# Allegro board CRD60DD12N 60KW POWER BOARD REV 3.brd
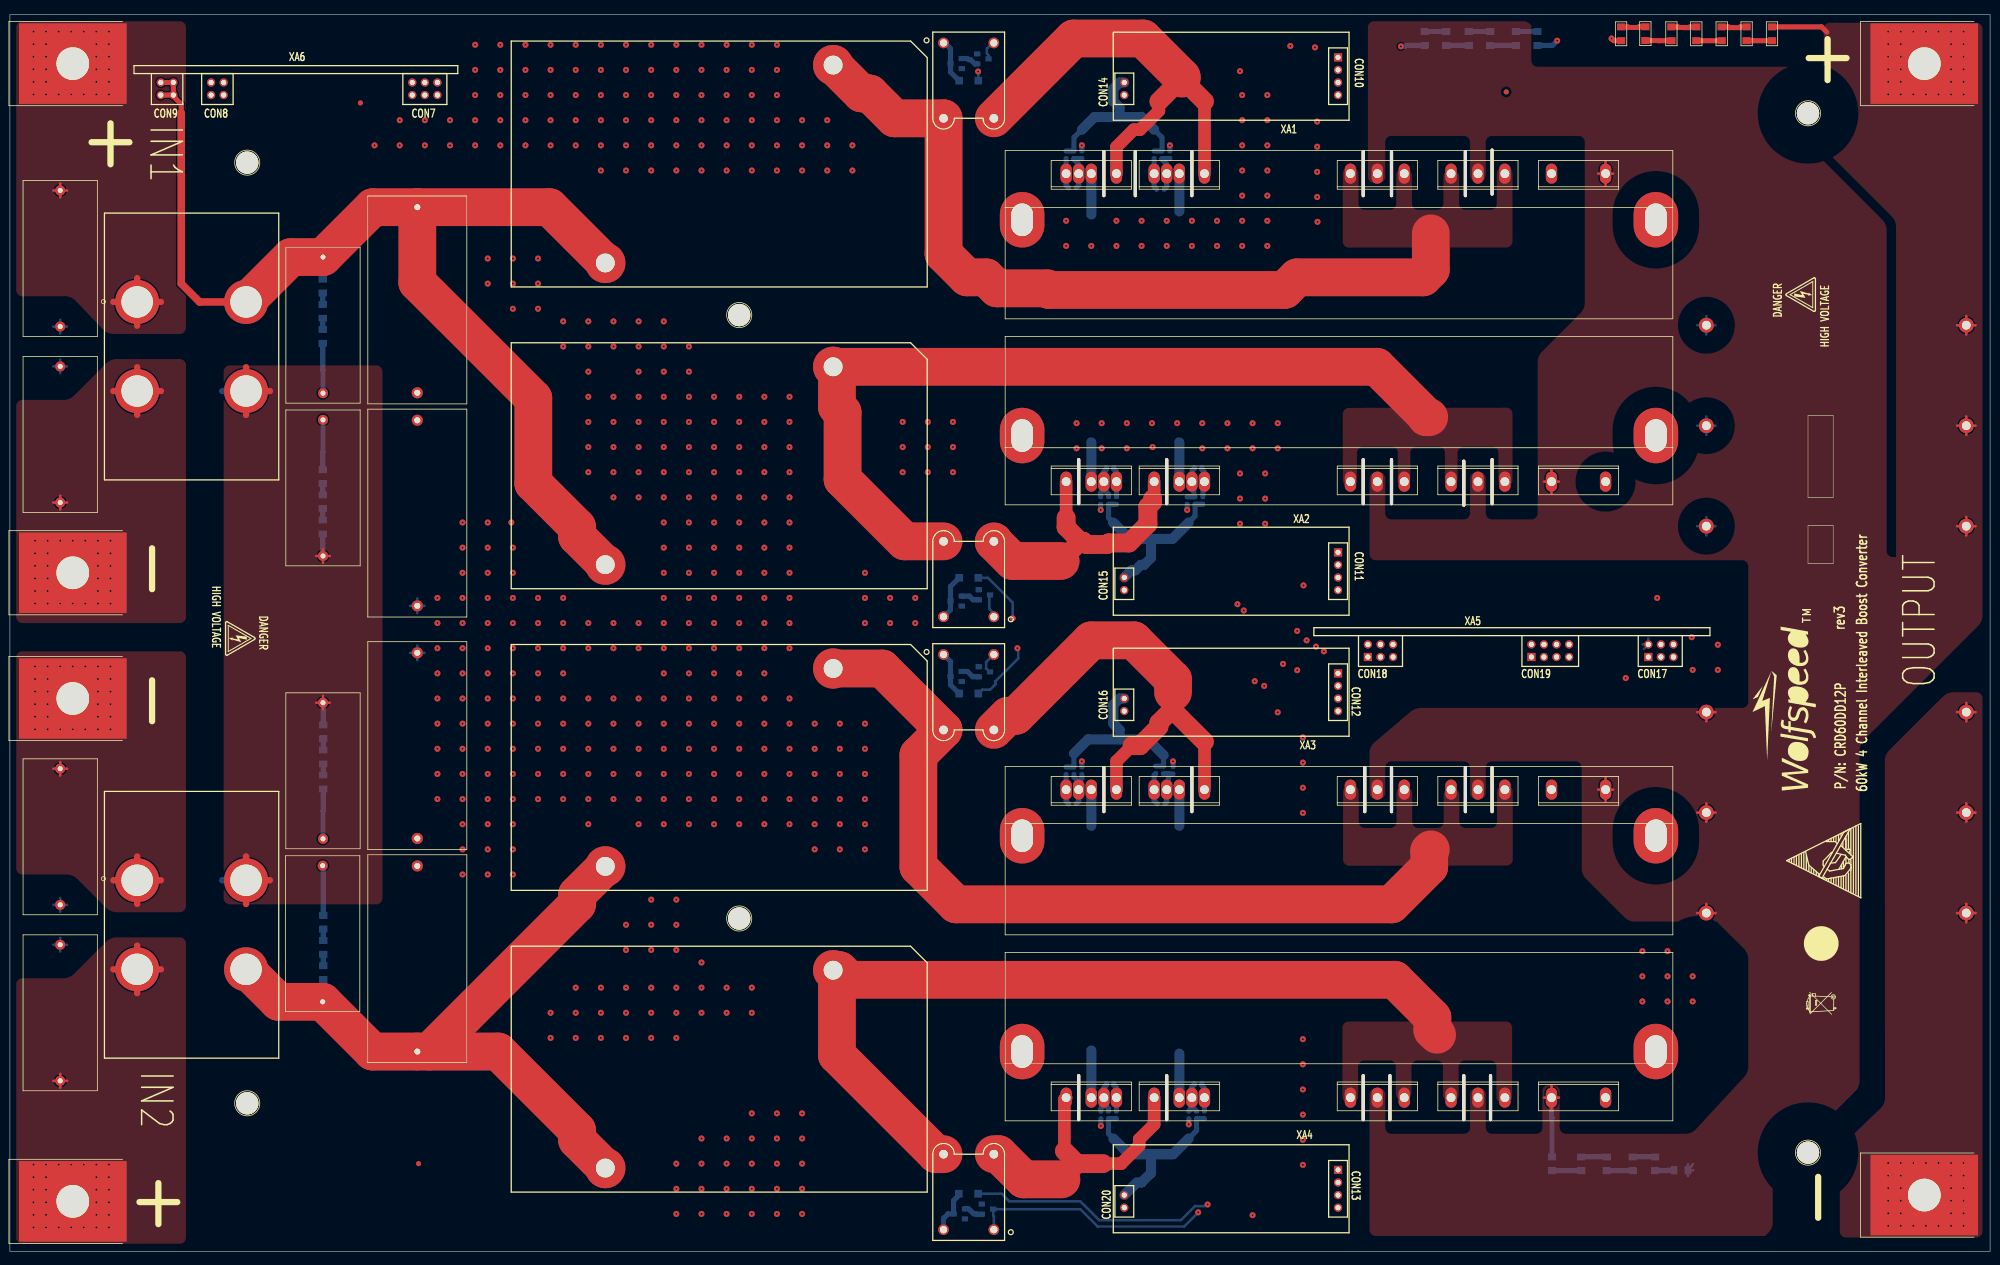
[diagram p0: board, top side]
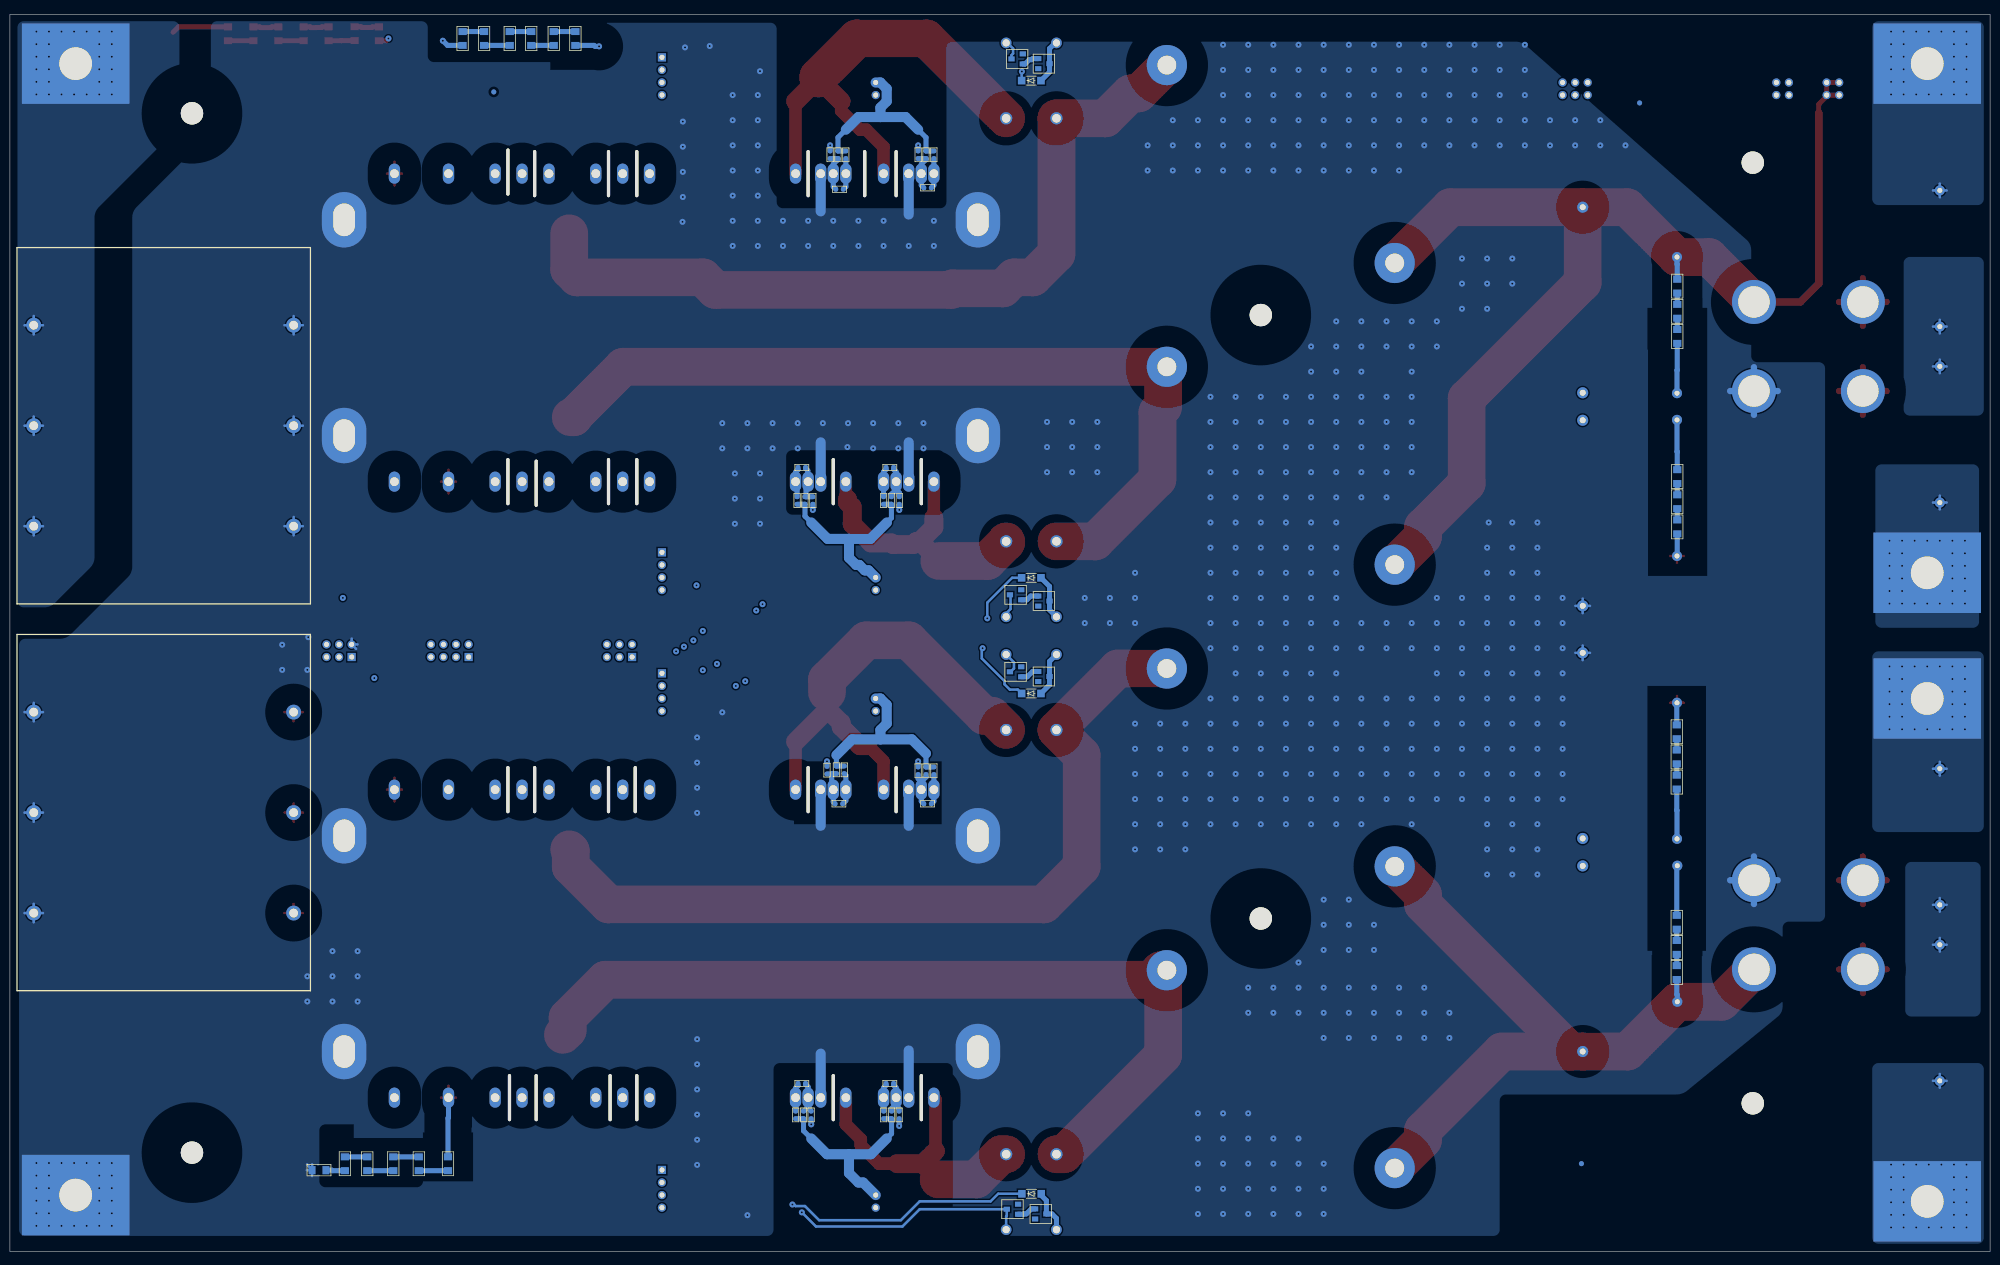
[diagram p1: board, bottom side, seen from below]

Outline 400 x 250 mm; copper layers: TOP, ART02, ART03, BOTTOM. Coordinates in mm from the lower left corner of the outline.
Outline path: rectangle 0,0 400,250

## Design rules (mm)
net group PH1H_SW: nets N02836 N03399
net group PH1L_SW: nets N08631 N08663
net group PH2H_SW: nets N12716 N12748
net group PH2L_SW: nets N13264 N13296
net group 1206_PAD: nets N05226 N09826 N10005 N10007 N12260 N12055866 N12061792 N12061794 N12062725 N12062727 N12099195 N12120580 N12122904 N12122941 N12122950 N12123059 N12123067
net group HVDC: nets HV_L1_IN HV_L3_IN N05349 N12168
net group LVDC: nets +12V_HV +12V_RTN N00267 V_IN_SENSE V_OUT_SENSE
net group PH1H_CTRL: nets G1H N01331 N01554 N02735 N03711 N03751 N12047025 PH1H_CS PH1H_CS_RTN PWM1H
net group PH1L_CTRL: nets G1L N08439 N08479 N08627 N08687 N08743 N12048829 PH1L_CS PH1L_CS_RTN PWM1L
net group PH2H_CTRL: nets G2H N12524 N12564 N12712 N12776 N12832 N12042408 PH2H_CS PH2H_CS_RTN PWM2H
net group PH2L_CTRL: nets G2L N13072 N13096 N13260 N13300 N13376 N12045153 PH2L_CS PH2L_CS_RTN PWM2L
nets with their own width: min track width 0.508; nets G1H_RTN G1L_RTN G2H_RTN G2L_RTN GND_SIGNAL N00134 N00143 N00161 N003141 N004301 N004861 N005141 N12176 N12212 N122921 N123081 N123401 N123561 PV_-VE

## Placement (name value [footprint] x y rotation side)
C1  22uF  [RAD_37MM5_L42_W20]  82.3 192.28 270 top
C2  22uF  [RAD_37MM5_L42_W20]  82.3 149.22 270 top
C3  22uF  [RAD_37MM5_L42_W20]  82.3 59.18 90 top
C4  22uF  [RAD_37MM5_L42_W20]  82.3 102.23 90 top
C5  100uF  [CAP_6L_52P5X20P3]  368.94 166.88 180 bottom
C6  100uF  [CAP_6L_52P5X20P3]  368.94 88.71 0 bottom
C9  1.5nF  [0603]  232.41 214.66 0 bottom
C10  1.5nF  [0603]  240.03 158.43 180 bottom
C19  1.5nF  [0603]  214.63 214.95 0 bottom
C20  1.5nF  [0603]  222.25 158.43 180 bottom
C21  1.5nF  [0603]  214.63 90.49 0 bottom
C22  1.5nF  [0603]  232.54 90.49 0 bottom
C23  1.5nF  [0603]  222.25 33.97 180 bottom
C24  1.5nF  [0603]  240.03 33.97 180 bottom
CON1  +PV_1  [PWR_CON_50A]  12.7 240.03 0 top
CON2  -PV_1  [PWR_CON_50A]  12.7 137.16 0 top
CON3  +PV_2  [PWR_CON_50A]  12.7 10.16 0 top
CON4  -PV_2  [PWR_CON_50A]  12.7 111.76 0 top
CON5  HVDC_OUT  [PWR_CON_50A]  386.71 240.03 0 top
CON6  PV_-VE  [PWR_CON_50A]  386.71 11.43 0 top
CT1  -  [CT_PE-67200NL]  193.68 236.6 90 top
CT2  -  [CT_PE-67200NL]  193.68 135.89 270 top
CT3  -  [CT_PE-67200NL]  193.68 113.03 90 top
CT4  -  [CT_PE-67200NL]  193.68 12.06 270 top
D1  C4D10120D  [TO-247-3L]  276.23 217.81 180 top
D2  C4D10120D  [TO-247-3L]  276.23 155.57 0 top
D3  C4D10120D  [TO-247-3L]  276.23 93.34 180 top
D4  C4D10120D  [TO-247-3L]  276.23 31.11 0 top
D11  BAS16  [SOT-23]  191.13 240.03 270 bottom
D12  BAV20W-7F  [SOD-123]  193.68 236.6 0 bottom
D15  BAS16  [SOT-23]  191.13 131.44 270 bottom
D16  BAV20W-7F  [SOD-123]  193.68 136.14 0 bottom
D19  BAS16  [SOT-23]  191.13 116.2 270 bottom
D20  BAV20W-7F  [SOD-123]  193.68 112.78 0 bottom
D23  BAS16  [SOT-23]  191.77 7.62 270 bottom
D24  BAV20W-7F  [SOD-123]  193.63 11.7 0 bottom
D25  C4D10120D  [TO-247-3L]  296.55 217.81 180 top
D26  C4D10120D  [TO-247-3L]  296.55 155.57 0 top
D27  C4D10120D  [TO-247-3L]  296.55 93.34 180 top
D28  C4D10120D  [TO-247-3L]  296.55 31.11 0 top
D29  DLA60I1200HA  [TO-247-2L]  316.87 217.81 180 top
D30  DLA60I1200HA  [TO-247-2L]  316.87 155.57 0 top
D31  DLA60I1200HA  [TO-247-2L]  316.87 93.34 180 top
D32  DLA60I1200HA  [TO-247-2L]  316.87 31.11 0 top
FB1  BEAD  [0603]  213.36 221.62 270 bottom
FB2  BEAD  [0603]  231.14 221.62 270 bottom
FB3  BEAD  [0603]  223.52 151.76 90 bottom
FB4  BEAD  [0603]  240.98 151.76 90 bottom
FB5  BEAD  [0603]  213.36 97.16 270 bottom
FB6  BEAD  [0603]  231.46 97.35 270 bottom
FB7  BEAD  [0603]  223.49 27.62 90 bottom
FB8  BEAD  [0603]  241.27 27.62 90 bottom
HS1  HEAT_SINK  [AAVID_78010_L135MM]  268.48 208.48 90 top
HS2  HEAT_SINK  [AAVID_78010_L135MM]  268.48 164.89 270 top
HS3  HEAT_SINK  [AAVID_78010_L135MM]  268.48 84.03 90 top
HS4  HEAT_SINK  [AAVID_78010_L135MM]  268.48 40.43 270 top
L1  INDUCTOR  [PWR_IND_T26586]  143.28 219.75 270 top
L2  INDUCTOR  [PWR_IND_T26586]  143.28 158.79 270 top
L3  INDUCTOR  [PWR_IND_T26586]  143.28 97.83 270 top
L4  INDUCTOR  [PWR_IND_T26586]  143.28 36.87 270 top
NOREF  -  []  82.55 17.78 0 top
NOREF#2  -  [unnamed#2]  233.68 155.57 90 top
NOREF#3  -  [unnamed#2]  273.37 31.11 90 top
NOREF#4  -  []  -155.26 -223.84 0 top
NOREF#5  -  [unnamed#2]  279.08 217.81 90 top
NOREF#6  -  [unnamed#2]  220.98 217.81 90 top
NOREF#7  -  []  365.66 62.76 90 top
NOREF#8  -  []  70.8 232.09 0 top
NOREF#9  -  [unnamed#2]  279.08 155.57 90 top
NOREF#10  -  [unnamed#2]  299.4 93.34 90 top
NOREF#11  -  [unnamed#2]  238.76 93.34 90 top
NOREF#12  -  []  369.43 79.51 90 top
NOREF#13  -  [unnamed#2]  233.68 31.11 90 top
NOREF#14  -  [unnamed#2]  220.98 93.34 90 top
NOREF#15  -  [unnamed#2]  279.08 93.34 90 top
NOREF#16  -  []  364.49 190.18 90 top
NOREF#17  -  []  365.77 52.72 90 top
NOREF#18  -  [unnamed#2]  273.37 217.81 90 top
NOREF#19  -  [unnamed#2]  47.94 220.03 0 top
NOREF#20  -  [unnamed#2]  299.4 218.12 90 top
NOREF#21  -  []  0 250 0 top
NOREF#22  -  [unnamed#2]  227.33 217.81 90 top
NOREF#23  -  []  302.26 234.31 0 top
NOREF#24  -  [unnamed#2]  299.08 31.11 90 top
NOREF#25  -  [unnamed#2]  294 217.81 90 top
NOREF#26  -  []  43.8 127.06 270 top
NOREF#27  -  [unnamed#2]  363.22 230 0 top
NOREF#28  -  [unnamed#2]  363.22 20 0 top
NOREF#29  -  []  0 0 90 top
NOREF#30  -  [unnamed#2]  294 93.34 90 top
NOREF#31  -  [unnamed#2]  215.9 155.57 90 top
NOREF#32  -  []  366.08 91.44 90 top
NOREF#33  -  [unnamed#2]  273.69 93.34 90 top
NOREF#34  -  [unnamed#2]  47.94 29.97 0 top
NOREF#35  -  [unnamed#2]  293.69 155.26 90 top
NOREF#36  -  [unnamed#2]  215.9 31.11 90 top
NOREF#37  -  [unnamed#2]  147.32 189.23 0 top
NOREF#38  -  [unnamed#2]  293.69 31.11 90 top
NOREF#39  -  [unnamed#2]  299.4 155.57 90 top
NOREF#40  -  [unnamed#2]  278.76 31.11 90 top
NOREF#41  -  [unnamed#2]  147.32 67.31 0 top
NOREF#42  -  []  -5.08 -44.45 0 top
NOREF#43  -  [unnamed#2]  238.76 217.81 90 top
NOREF#44  -  [unnamed#2]  273.37 155.57 90 top
Q1  NMOS 4-lead  [TO-247-4L]  218.44 217.81 180 top
Q2  NMOS 4-lead  [TO-247-4L]  236.22 217.81 180 top
Q3  NMOS 4-lead  [TO-247-4L]  218.44 155.57 0 top
Q4  NMOS 4-lead  [TO-247-4L]  236.22 155.57 0 top
Q5  NMOS 4-lead  [TO-247-4L]  218.44 93.34 180 top
Q6  NMOS 4-lead  [TO-247-4L]  236.22 93.34 180 top
Q7  NMOS 4-lead  [TO-247-4L]  218.44 31.11 0 top
Q8  NMOS 4-lead  [TO-247-4L]  236.22 31.11 0 top
R1  1R  [0603]  216.53 221.62 90 bottom
R2  1R  [0603]  234.31 221.62 90 bottom
R3  1R  [0603]  220.34 151.76 270 bottom
R4  1R  [0603]  237.81 151.76 270 bottom
R5  1R  [0603]  216.53 97.16 90 bottom
R6  1R  [0603]  234.95 97.28 90 bottom
R7  10K  [0603]  214.95 221.62 270 bottom
R8  1R  [0603]  220.37 27.62 270 bottom
R9  1R  [0603]  238.15 27.62 270 bottom
R10  10K  [0603]  232.73 221.62 270 bottom
R11  200K  [1206]  325.46 246.06 270 top
R12  1.07M  [1206]  340.65 246.06 90 top
R13  10K  [0603]  221.93 151.76 90 bottom
R14  1.07M  [1206]  285.78 245.11 90 bottom
R15  1.07M  [1206]  290.14 245.11 270 bottom
R16  10K  [0603]  239.4 151.76 90 bottom
R17  1.07M  [1206]  294.69 245.11 90 bottom
R18  1.07M  [1206]  299.03 245.11 270 bottom
R19  10K  [0603]  214.95 97.16 270 bottom
R20  1.07M  [1206]  304.22 245.11 90 bottom
R21  1.07M  [1206]  308.56 245.11 270 bottom
R22  10K  [0603]  233.04 97.35 270 bottom
R25  10K  [0603]  221.91 27.62 90 bottom
R28  10K  [0603]  239.69 27.62 90 bottom
R29  1.07M  [1206]  63.2 195.07 270 bottom
R30  1.07M  [1206]  63.2 189.99 270 bottom
R31  1.07M  [1206]  63.2 184.91 270 bottom
R32  1.07M  [1206]  63.2 156.59 270 bottom
R33  1.07M  [1206]  63.2 151.51 270 bottom
R34  1.07M  [1206]  63.2 146.43 270 bottom
R35  1.07M  [1206]  63.3 56.39 90 bottom
R36  1.07M  [1206]  63.3 61.47 90 bottom
R37  1.07M  [1206]  63.3 66.55 90 bottom
R38  1.07M  [1206]  63.3 94.87 90 bottom
R39  1.07M  [1206]  63.3 99.95 90 bottom
R40  1.07M  [1206]  63.3 105.03 90 bottom
R41  1.07M  [1206]  311.51 17.75 270 bottom
R42  1.07M  [1206]  317.4 17.75 90 bottom
R43  1.07M  [1206]  322.55 17.75 270 bottom
R44  1.07M  [1206]  327.81 17.75 90 bottom
R45  1.07M  [1206]  332.33 17.75 270 bottom
R46  1.07M  [1206]  337.57 16.46 0 bottom
R59  1.07M  [1206]  355.94 246.06 270 top
R60  1.07M  [1206]  350.81 246.06 90 top
R61  1.07M  [1206]  345.78 246.06 270 top
R63  1.07M  [1206]  335.62 246.06 270 top
R64  1.07M  [1206]  330.37 246.09 90 top
XA1  CGD15SG00D2_Gate Driver  [CGD15SG00D2_GATE_DRIVER]  268.29 241.3 180 top
XA2  CGD15SG00D2_Gate Driver  [CGD15SG00D2_GATE_DRIVER]  268.29 141.29 180 top
XA3  CGD15SG00D2_Gate Driver  [CGD15SG00D2_GATE_DRIVER]  268.29 116.84 180 top
XA4  CGD15SG00D2_Gate Driver  [CGD15SG00D2_GATE_DRIVER]  268.29 16.51 180 top
XA5  -  [CRD50DD12N_CTRL]  274.32 120.14 0 top
XA6  FLYBACK_PS  [FLYBACK_DAUGHTER_BRD]  30.48 233.68 0 top
XC1  2.2uF  [RAD_27MM5_L31_5_W15]  10.16 200.66 270 top
XC2  2.2uF  [RAD_27MM5_L31_5_W15]  10.16 165.1 270 top
XC3  2.2uF  [RAD_27MM5_L31_5_W15]  63.25 187.2 270 top
XC4  2.2uF  [RAD_27MM5_L31_5_W15]  63.25 154.31 270 top
XC5  2.2uF  [RAD_27MM5_L31_5_W15]  10.16 48.26 90 top
XC6  2.2uF  [RAD_27MM5_L31_5_W15]  10.16 83.82 90 top
XC7  2.2uF  [RAD_27MM5_L31_5_W15]  63.18 64.23 90 top
XC8  2.2uF  [RAD_27MM5_L31_5_W15]  63.25 97.16 90 top
XL1  CHOKE CM  [CM_CHOKE_T46592]  36.7 182.88 270 top
XL2  CHOKE CM  [CM_CHOKE_T46592]  36.7 66.04 270 top
ZD5  33V  [SOT-23]  196.53 240.98 90 bottom
ZD6  33V  [SOT-23]  196.85 132.72 90 bottom
ZD7  33V  [SOT-23]  196.85 117.16 90 bottom
ZD8  33V  [SOT-23]  197.49 8.57 90 bottom

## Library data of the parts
C1-C4 C9 C10 C19-C24 XC1-XC8 = CAPACITOR NON-POL
C5 C6 = CAP NP 6L
CON1-CON6 = T POINT S_0
CT1-CT4 = CT_PE-67200NL
D1-D4 D25-D28 = C4D10120D
D11 D15 D19 D23 = DIODE_SO-23
D12 D16 D20 D24 = DIODE SCHOTTKY
D29-D32 = DIODE_2
FB1-FB8 = BEAD
HS1-HS4 = HEAT_SINK_2
L1-L4 = INDUCTOR FERRITE_0
Q1-Q8 = NMOS 4-lead
R1-R22 R25 R28-R46 R59-R61 R63 R64 = RESISTOR
XA1-XA4 = CGD15SG00D2_Gate Driver_0
XA5 = CRD50DD12N_CTRL
XA6 = FLYBACK_PS
XL1 XL2 = CHOKE CM
ZD5-ZD8 = DIODE ZENER SO-23

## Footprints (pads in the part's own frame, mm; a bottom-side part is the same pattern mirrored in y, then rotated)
0603
  rect 0.762x0.813 smd: 1(-0.762,0) 2(0.762,0)
1206
  rect 1.397x1.651 smd: 1(-1.397,0) 2(1.397,0)
AAVID_78010_L135MM
  oval 11.201x8.992 hole 6.604x4.394: 1(0,-64.008) 2(0,64.008)
CAP_6L_52P5X20P3
  round 2.997 hole 1.778: 1(-26.251,20.3) 2(26.251,20.3) 3(-26.251,0) 4(26.251,0) 5(-26.251,-20.3) 6(26.251,-20.3)
CGD15SG00D2_GATE_DRIVER
  rect 1.651x1.651 hole 1.041: 1(0,0)
  round 1.651 hole 1.041: 2(0,2.54) 3(0,5.08) 4(0,7.62) 5(43.18,5.08) 6(43.18,7.62)
CM_CHOKE_T46592
  round 8.89 hole 6.35: 1(-9,-11) 2(9,-11) 3(9,11) 4(-9,11)
CRD50DD12N_CTRL
  rect 1.651x1.651 hole 1.041: 1(0,0) 7(33.02,0) 15(56.642,0)
  round 1.651 hole 1.041: 2(0,2.54) 3(2.54,0) 4(2.54,2.54) 5(5.08,0) 6(5.08,2.54) 8(33.02,2.54) 9(35.56,0) 10(35.56,2.54) 11(38.1,0) 12(38.1,2.54) 13(40.64,0) 14(40.64,2.54) 16(56.642,2.54) 17(59.182,0) 18(59.182,2.54) 19(61.722,0) 20(61.722,2.54)
CT_PE-67200NL
  round 2.464 hole 1.753: 1(-7.62,5.08) 2(-7.62,-5.08)
  round 2.159 hole 1.473: 3(7.62,5.08) 4(7.62,-5.08)
FLYBACK_DAUGHTER_BRD
  round 1.651 hole 1.041: 1(0,0) 2(0,2.54) 3(2.54,0) 4(2.54,2.54) 5(10.16,0) 6(10.16,2.54) 7(12.7,0) 8(12.7,2.54) 9(50.8,0) 10(50.8,2.54) 11(53.34,0) 12(53.34,2.54) 13(55.88,0) 14(55.88,2.54)
PWR_CON_50A
  rect 21.717x16.256 hole 6.604: 1(0,0)
PWR_IND_T26586
  round 8.128 hole 3.81: 1(-19.99,23.012) 3(19.99,-23.012)
RAD_27MM5_L31_5_W15
  round 2.032 hole 1.016: 1(-13.75,0) 2(13.75,0)
RAD_37MM5_L42_W20
  round 2.235 hole 1.219: 1(-18.75,0) 2(18.75,0)
SOD-123
  rect 1.524x1.549 smd: 1(-1.95,0) 2(1.95,0)
SOT-23
  rect 1.016x1.27 smd: 1(-1.016,-1.143) 2(1.016,-1.143) 3(0,1.143)
TO-247-2L
  oval 2.286x4.064 hole 1.778: 1(-5.461,0) 2(5.461,0)
TO-247-3L
  oval 2.286x4.064 hole 1.778: 1(-5.436,0) 2(0,0) 3(5.436,0)
TO-247-4L
  oval 2.286x4.064 hole 1.778: 1(-5.08,0) 2(0,0) 3(2.54,0) 4(5.08,0)
unnamed#2
  oval 9.525x0.635 hole 10.16x1.27 unplated: (0,0)

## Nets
+12V_HV: XA1.1(VCC) XA2.1(VCC) XA3.1(VCC) XA4.1(VCC) XA5.15(17.1) XA6.10(+DC_OUT1) XA6.12(+DC_OUT2) XA6.14(+DC_OUT3)
+12V_RTN: XA1.2(RTN) XA2.2(RTN) XA3.2(RTN) XA4.2(RTN) XA5.18(17.4) XA6.9(-DC_OUT1) XA6.11(-DC_OUT2) XA6.13(-DC_OUT3)
GND_SIGNAL: XA1.3(PWM-) XA2.3(PWM-) XA3.3(PWM-) XA4.3(PWM-) XA5.1(18.1) XA5.6(18.6) XA5.20(17.6)
G1H: FB1.1 FB2.1 R7.1 R10.1 XA1.5(GATE)
G1H_RTN: R1.2 R2.2 XA1.6(SOURCE)
G1L: FB3.1 FB4.1 R13.1 R16.1 XA2.5(GATE)
G1L_RTN: R3.2 R4.2 XA2.6(SOURCE)
G2H: FB5.1 FB6.1 R19.1 R22.1 XA3.5(GATE)
G2H_RTN: R5.2 R6.2 XA3.6(SOURCE)
G2L: FB7.1 FB8.1 R25.1 R28.1 XA4.5(GATE)
G2L_RTN: R8.2 R9.2 XA4.6(SOURCE)
HV_L1_IN: C1.1 D29.2(A) D30.2(A) L1.3 L2.3 R14.1 R29.1 XA6.1(+DC_IN1) XA6.2(+DC_IN2) XA6.3(+DC_IN3) XA6.4(+DC_IN4) XC3.1 XL1.4
HV_L3_IN: C3.1 D31.2(A) D32.2(A) L3.3 L4.3 R35.1 XC7.1 XL2.3
PH1H_CS: D12.2(CATHODE) XA5.7(19.1)
PH1H_CS_RTN: CT1.4 XA5.9(19.3) ZD5.3(CATHODE)
PH1L_CS: D16.2(CATHODE) XA5.11(19.5)
PH1L_CS_RTN: CT2.3 XA5.13(19.7) ZD6.3(CATHODE)
PH2H_CS: D20.2(CATHODE) XA5.8(19.2)
PH2H_CS_RTN: CT3.4 XA5.10(19.4) ZD7.3(CATHODE)
PH2L_CS: D24.2(CATHODE) XA5.12(19.6)
PH2L_CS_RTN: CT4.3 XA5.14(19.8) ZD8.3(CATHODE)
PV_-VE: C2.2 C4.2 C5.2 C5.4 C5.6 C6.2 C6.4 C6.6 CON6.1(TP) HS1.1 HS1.2 HS2.1 HS2.2 HS3.1 HS3.2 HS4.1 HS4.2 Q1.2(S1) Q2.2(S1) Q3.2(S1) Q4.2(S1) Q5.2(S1) Q6.2(S1) Q7.2(S1) Q8.2(S1) R34.2 R40.2 R46.2 XA5.16(17.2) XA6.5(-DC_IN1) XA6.6(-DC_IN2) XA6.7(-DC_IN3) XA6.8(-DC_IN4) XC4.2 XC8.2 XL1.3 XL2.4
PWM1H: XA1.4(PWM+) XA5.3(18.3)
PWM1L: XA2.4(PWM+) XA5.5(18.5)
PWM2H: XA3.4(PWM+) XA5.2(18.2)
PWM2L: XA4.4(PWM+) XA5.4(18.4)
V_IN_SENSE: R21.2 XA5.19(17.5)
V_OUT_SENSE: R11.2 XA5.17(17.3)
N00134: CON1.1(TP) XC1.1 XL1.1
N00143: CON2.1(TP) XC2.2 XL1.2
N00161: XC1.2 XC2.1
N00267: C1.2 C2.1 R31.2 R32.1 XC3.2 XC4.1
N01331: C19.1 FB1.2 Q1.4(G)
N01554: C19.2 Q1.3(S2) R1.1 R7.2
N02735: CT1.3 D11.3(K) D12.1(ANODE)
N02836: CT1.2 Q1.1(D) Q2.1(D)
N003141: R29.2 R30.1
N03399: CT1.1 D1.1 D1.3 D25.1 D25.3 L1.1
N03711: C9.1 FB2.2 Q2.4(G)
N03751: C9.2 Q2.3(S2) R2.1 R10.2
N004301: R30.2 R31.1
N004861: R32.2 R33.1
N005141: R33.2 R34.1
N05226: R12.2 R63.1
N05349: C5.1 C5.3 C5.5 C6.1 C6.3 C6.5 CON5.1(TP) D1.2 D2.2 D3.2 D4.2 D25.2 D26.2 D27.2 D28.2 D29.1(K) D30.1(K) D31.1(K) D32.1(K) R41.1 R59.1
N08439: C20.1 FB3.2 Q3.4(G)
N08479: C20.2 Q3.3(S2) R3.1 R13.2
N08627: CT2.4 D15.3(K) D16.1(ANODE)
N08631: CT2.1 Q3.1(D) Q4.1(D)
N08663: CT2.2 D2.1 D2.3 D26.1 D26.3 L2.1
N08687: C10.1 FB4.2 Q4.4(G)
N08743: C10.2 Q4.3(S2) R4.1 R16.2
N09826: R43.2 R44.1
N10005: R63.2 R64.1
N10007: R60.2 R61.1
N12168: CON3.1(TP) XC5.1 XL2.2
N12176: CON4.1(TP) XC6.2 XL2.1
N12212: XC5.2 XC6.1
N12260: C3.2 C4.1 R37.2 R38.1 XC7.2 XC8.1
N12524: C21.1 FB5.2 Q5.4(G)
N12564: C21.2 Q5.3(S2) R5.1 R19.2
N12712: CT3.3 D19.3(K) D20.1(ANODE)
N12716: CT3.2 Q5.1(D) Q6.1(D)
N12748: CT3.1 D3.1 D3.3 D27.1 D27.3 L3.1
N12776: C22.1 FB6.2 Q6.4(G)
N12832: C22.2 Q6.3(S2) R6.1 R22.2
N13072: C23.1 FB7.2 Q7.4(G)
N13096: C23.2 Q7.3(S2) R8.1 R25.2
N13260: CT4.4 D23.3(K) D24.1(ANODE)
N13264: CT4.1 Q7.1(D) Q8.1(D)
N13296: CT4.2 D4.1 D4.3 D28.1 D28.3 L4.1
N13300: C24.1 FB8.2 Q8.4(G)
N13376: C24.2 Q8.3(S2) R9.1 R28.2
N122921: R35.2 R36.1
N123081: R36.2 R37.1
N123401: R38.2 R39.1
N123561: R39.2 R40.1
N12042408: D19.1(A) ZD7.1(ANODE)
N12045153: D23.1(A) ZD8.1(ANODE)
N12047025: D11.1(A) ZD5.1(ANODE)
N12048829: D15.1(A) ZD6.1(ANODE)
N12055866: R59.2 R60.1
N12061792: R41.2 R42.1
N12061794: R42.2 R43.1
N12062725: R44.2 R45.1
N12062727: R45.2 R46.1
N12099195: R12.1 R61.2
N12120580: R11.1 R64.2
N12122904: R17.2 R18.1
N12122941: R20.2 R21.1
N12122950: R18.2 R20.1
N12123059: R15.2 R17.1
N12123067: R14.2 R15.1

Pads without a net: D11 2; D15 2; D19 2; D23 2; ZD5 2; ZD6 2; ZD7 2; ZD8 2

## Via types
v1: diameter 1.219, hole 0.406, TOP to BOTTOM, 710 vias

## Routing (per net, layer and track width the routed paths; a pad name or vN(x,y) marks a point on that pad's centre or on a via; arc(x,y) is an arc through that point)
+12V_HV: length 859.2
  ART02 w1.016: v1(251.46,115.25) 252.09,115.25 252.73,115.89 254,115.89 254.63,115.25 267.02,115.25 268.29,116.52 ; 268.29,116.52 XA3.1 ; 268.29,116.52 269.88,114.94 269.88,114.62 272.73,111.76 322.58,111.76 324.8,113.98 324.8,116.95 325.75,117.91 328.73,117.91 XA5.15 328.93,122.17 328.93,127.95 330.52,129.54 344.17,129.54 348.93,134.3 348.93,215.9 321.63,243.21 312.1,243.21 311.15,244.16 311.15,245.11 308.29,247.97 92.71,247.97 86.36,241.62 XA6.14 XA6.12 XA6.10
  ART03 w1.016: XA6.10 XA6.12 XA6.14 86.36,241.62 92.71,247.97 250.19,247.97 256.86,241.3 XA1.1 ; XA2.1 268.29,140.97 266.7,139.38 266.7,139.06 262.89,135.25 262.89,125.73 263.21,125.41 263.21,125.09 265.43,122.87 265.75,122.87 267.65,120.97 267.65,117.47 XA3.1 ; v1(251.46,115.25) 251.46,10.16 256.54,5.08 270.29,5.08 271.3,6.1 271.3,6.19 272.73,7.62 272.73,7.94 273.05,8.26 273.05,13.65 270.19,16.51 XA4.1
+12V_RTN: length 844.9
  ART02 w1.016: v1(326.39,115.89) 326.39,113.35 323.21,110.17 272.1,110.17 268.29,113.98 XA3.2 267.65,113.67 254,113.67 v1(253.37,114.3) ; XA6.9 XA6.11 XA6.13 86.36,234.47 86.52,234.63 87,234.63 87.95,235.59 87.95,240.03 94.3,246.38 307.5,246.38 309.56,244.32 309.56,243.52 311.47,241.62 320.99,241.62 347.35,215.26 347.35,135.89 343.54,132.08 v1(332.74,132.08)
  ART03 w1.016: 332.74,126.22 331.11,126.22 326.39,121.5 v1(326.39,115.89) ; 332.74,126.22 v1(332.74,132.08) ; 332.74,126.22 333.5,125.46 XA5.18 ; XA3.2 268.29,114.62 269.88,116.2 269.88,117.47 269.24,118.11 269.24,121.6 266.38,124.46 266.06,124.46 264.8,125.73 264.8,126.05 264.48,126.36 264.48,134.62 268.29,138.43 XA2.2 ; XA6.9 XA6.11 XA6.13 86.68,233.68 87.95,234.95 87.95,240.03 91.44,243.52 91.44,243.84 93.98,246.38 249.56,246.38 257.18,238.76 XA1.2 ; v1(253.37,114.3) 253.37,10.79 257.18,6.99 269.62,6.99 271.49,8.86 271.49,11.72 269.24,13.97 XA4.2
GND_SIGNAL: length 273.1
  ART03 w0.508: XA5.1 275.37,120.14 ; XA5.1 274.32,121.2 ; XA5.1 273.27,120.14 ; XA5.1 274.32,119.09 ; 336.04,121.63 XA5.20 ; XA5.20 337.1,122.68 ; XA5.20 334.99,122.68 ; XA5.20 336.04,123.74 ; 279.4,121.63 XA5.6 ; XA5.6 279.4,123.74 ; XA5.6 280.45,122.68 ; XA5.6 278.35,122.68
  ART03 w1.016: XA1.3 269.24,236.22 270.35,235.11 270.35,233.52 268.92,232.09 261.94,232.09 261.3,231.46 261.3,150.5 270.03,141.76 270.03,137.95 XA2.3 266.22,134.14 266.22,126.84 269.24,123.83 270.19,123.83 ; 274.32,114.94 271.14,111.76 XA3.3 269.88,110.17 269.88,108.58 268.92,107.63 258.76,107.63 256.22,105.09 256.22,12.45 257.24,11.43 XA4.3
G1H: length 38.8
  BOTTOM w1.016: 231.14,226.69 232.73,225.11 R10.1 FB2.1 ; 216.53,226.69 214.95,225.11 R7.1 FB1.1
  BOTTOM w2.032: 224.16,229.24 224.16,231.14 222.88,232.41 222.88,234.95 224.16,236.22 XA1.5 ; 224.16,229.24 219.07,229.24 216.53,226.69 ; 224.16,229.24 228.6,229.24 231.14,226.69
G1H_RTN: length 6.5
  ART03 w0.508: 225.11,232.63 XA1.6 ; XA1.6 224.05,233.68 ; XA1.6 226.16,233.68 ; XA1.6 225.11,234.73
  BOTTOM w1.016: R2.2 v1(234.31,223.52) ; v1(216.53,223.52) R1.2
G1L: length 40.3
  BOTTOM w1.016: 222.85,147.32 221.93,148.24 R13.1 FB3.1 ; 238.12,147.32 239.4,148.59 R16.1 FB4.1
  BOTTOM w2.032: XA2.5 226.55,137.65 227.33,137.65 228.42,138.75 229.07,138.75 230.5,140.18 230.5,144 ; 238.12,147.32 234.81,144 230.5,144 ; 230.5,144 226.17,144 222.85,147.32
G1L_RTN: length 6.5
  ART03 w0.508: XA2.6 226.16,133.67 ; XA2.6 225.11,132.61 ; XA2.6 225.11,134.72 ; XA2.6 224.05,133.67
  BOTTOM w1.016: v1(220.34,149.86) R3.2 ; v1(237.81,149.86) R4.2
G2H: length 39
  BOTTOM w1.016: 214.95,100.65 R19.1 FB5.1 ; FB6.1 R22.1 233.04,100.33
  BOTTOM w2.032: XA3.5 224.15,111.76 222.88,110.49 222.88,106.68 224.16,105.41 224.16,103.5 ; 224.16,103.5 217.81,103.5 214.95,100.65 ; 224.16,103.5 229.87,103.5 233.04,100.33
G2H_RTN: length 6.4
  ART03 w0.508: XA3.6 225.11,110.27 ; XA3.6 224.05,109.22 ; XA3.6 225.11,108.17 ; XA3.6 226.16,109.22
  BOTTOM w1.016: v1(234.95,99.06) R6.2 ; R5.2 v1(216.53,99.06)
G2L: length 41.1
  BOTTOM w1.016: 238.12,22.86 239.69,24.42 R28.1 FB8.1 ; 222.88,22.86 221.91,23.84 R25.1 FB7.1
  BOTTOM w2.032: 230.5,19.68 230.5,15.88 228.6,13.97 227.65,13.97 XA4.5 ; 230.5,19.68 234.95,19.68 238.12,22.86 ; 230.5,19.68 226.06,19.68 222.88,22.86
G2L_RTN: length 6.8
  ART03 w0.508: 224.05,8.89 XA4.6 ; XA4.6 226.16,8.89 ; XA4.6 225.11,9.94 ; XA4.6 225.11,7.84
  BOTTOM w1.016: R9.2 238.15,25.74 v1(238.12,25.72) ; v1(220.37,25.4) R8.2
HV_L1_IN: length 914.4
  TOP w1.016: XA6.1 XA6.3 ; XA6.3 XA6.4 XA6.2 ; XA6.3 33.02,233.43 34.61,231.84 34.61,230.12
  TOP w1.524: XL1.4 38.31,191.88 34.61,195.58 34.61,230.12
  TOP w7.62: L1.3 109,211.03 C1.1 ; XL1.4 56.77,200.95 XC3.1 73.33,211.03 C1.1 ; C1.1 82.3,195.83 105.73,172.4 105.73,155.25 114.56,146.42 114.56,144.51 L2.3
  ART02 w4.191: D30.2 321.6,156.3 321.6,165.44 303.53,183.51
  ART02 w5.08: D29.2 310.83,217.23 310.83,190.82 303.53,183.51
  ART02 w7.62: C1.1 73.33,211.03 XC3.1 62.9,201.29 57.15,201.29 47.73,191.88 XL1.4 ; C1.1 108.69,211.03 119.96,199.76 L1.3 ; C1.1 82.61,210.71 82.61,195.2 105.73,172.09 105.73,155.25 114.56,146.42 114.56,144.51 L2.3
  ART02 w10.922: L1.3 127.15,206.64 128.42,206.64 132.04,210.26 171.05,210.26 195.44,185.88 297.04,185.88 299.4,183.51 303.53,183.51
  ART03 w1.016: v1(280.99,243.52) 282.89,241.62 307.02,241.62 311.4,237.24 311.4,217.87
  ART03 w2.54: D29.2 311.4,217.87
  ART03 w7.62: C1.1 82.3,195.83 105.73,172.4 105.73,155.25 114.56,146.42 114.56,144.51 L2.3 ; C1.1 109,211.03 L1.3 ; C1.1 73.29,211 XC3.1 62.96,200.66 56.52,200.66 47.73,191.88 XL1.4
  BOTTOM w1.016: v1(280.99,243.52) 281.81,243.52 282,243.71 285.78,243.71 ; R29.1 63.2,199.47 63.25,199.53 XC3.1
HV_L3_IN: length 710.3
  TOP w7.62: 84.77,40.43 114.56,70.22 114.56,72.13 L3.3 ; 84.77,40.43 C3.1 73.23,40.43 XC7.1 54.26,50.48 XL2.3 ; 84.77,40.43 98.62,40.43 114.56,24.5 114.56,22.59 L4.3
  ART02 w3.81: 322.33,51.37 313.69,60.01
  ART02 w4.191: 311.4,62.93 D31.2 ; 312.13,62.21 312.13,61.57 313.69,60.01 ; D32.2 322.33,51.37
  ART02 w7.62: 121.03,16.88 121.54,17.39 121.54,17.52 98.62,40.43 84.77,40.43 ; 84.77,40.43 C3.1 73.03,40.43 63.18,50.27 XC7.1 62.87,50.16 53.98,50.16 47.7,56.44 XL2.3 ; 84.77,40.43 114.56,70.22 114.56,72.13 L3.3
  ART02 w10.922: L4.3 121.54,16.88 143.08,38.42 172,38.42 196.51,62.93 311.4,62.93 312.13,62.21
  ART03 w7.62: L3.3 114.56,72.13 114.56,70.22 84.77,40.43 ; 84.77,40.43 C3.1 73.23,40.43 XC7.1 54.26,50.48 XL2.3 ; 84.77,40.43 98.62,40.43 114.56,24.5 114.56,22.59 L4.3
  BOTTOM w1.016: R35.1 63.3,51.99 63.18,51.87 XC7.1
PH1H_CS: length 240.7
  ART02 w0.508: XA5.7 307.34,117.54 306.32,116.52 274,116.52 270.83,119.7 257.68,119.7 257.18,119.19 v1(257.18,118.75)
  ART03 w0.508: v1(195.58,238.44) 196.52,238.44 201.92,243.84 248.28,243.84 257.18,234.95 v1(257.18,118.75)
  BOTTOM w0.508: v1(195.58,238.44) 195.62,238.4 D12.2
PH1H_CS_RTN: length 242.4
  ART02 w0.508: XA5.9 309.88,116.9 308.24,115.25 273.21,115.25 270.03,118.43 267.97,118.43 267.65,118.11 260.67,118.11 v1(260.03,117.47)
  ART03 w0.508: CT1.4 199.01,244.47 200.66,244.47 201.29,245.11 248.92,245.11 258.76,235.27 258.76,119.7 260.03,118.43 v1(260.03,117.47)
  BOTTOM w0.508: ZD5.3 197.68,241.74 197.36,242.06 197.36,243.08 198.5,244.22 CT1.4
PH1L_CS: length 165.7
  ART02 w0.508: XA5.11 312.42,119.06 314.32,117.16 315.6,117.16 318.93,120.49 318.93,137.32 311.15,145.1 244.16,145.1 226.69,127.64 206.06,127.64 205.74,127.95 v1(202.56,127.95)
  BOTTOM w0.508: v1(202.56,127.95) 202.56,131.13 197.55,136.14 D16.2
PH1L_CS_RTN: length 152.4
  ART02 w0.508: XA5.13 316.67,120.14 317.34,120.81 317.34,136.05 309.88,143.51 244.79,143.51 227.65,126.36 201.3,126.36 199.39,128.27 CT2.3
  BOTTOM w0.508: ZD6.3 197.87,132.72 197.87,129.85 198.75,128.96 CT2.3
PH2H_CS: length 125.2
  ART02 w0.508: v1(203.52,121.92) 205.42,123.83 242.25,123.83 246.38,127.95 247.65,127.95 248.28,127.32 251.14,127.32 252.41,128.59 305.12,128.59 307.34,126.36 XA5.8
  BOTTOM w0.508: v1(203.52,121.92) 203.68,121.76 203.68,119.86 199.08,115.26 199.08,114.63 198.02,113.56 196.41,113.56 D20.2
PH2H_CS_RTN: length 125.7
  ART02 w0.508: XA5.10 309.88,127.32 307.34,129.86 252.09,129.86 250.82,128.59 248.6,128.59 247.97,129.22 246.06,129.22 241.94,125.09 204.79,125.09 203.36,123.67 203.08,123.67 200.07,120.65 CT3.4
  BOTTOM w0.508: ZD7.3 197.87,117.16 197.18,117.85 197.18,119.07 CT3.4
PH2L_CS: length 243.1
  ART02 w0.508: v1(249.24,129.54) 249.24,130.02 250.35,131.13 308.29,131.13 312.42,127 XA5.12
  ART03 w0.508: v1(241.94,9.53) 249.24,16.83 v1(249.24,129.54)
  BOTTOM w0.508: v1(241.94,9.53) 241.62,9.53 241.3,9.21 239.4,9.21 236.54,6.35 220.03,6.35 216.22,10.16 201.9,10.16 200.37,11.7 D24.2
PH2L_CS_RTN: length 251.6
  ART02 w0.508: XA5.14 315.61,123.33 315.61,126.51 309.09,133.03 270.19,133.03 269.56,132.4 260.99,132.4 259.71,133.67 249.4,133.67 247.97,132.24 v1(247.97,130.81)
  ART03 w0.508: v1(240.03,7.94) 240.03,9.56 247.68,17.21 247.68,130.52 v1(247.97,130.81)
  BOTTOM w0.508: CT4.3 198.75,7.12 198.63,7.25 ZD8.3 216.22,8.57 219.71,5.08 237.17,5.08 v1(240.03,7.94)
PV_-VE: length 461.6
  TOP w0.508: 61.87,140.55 XC4.2 ; XC4.2 63.25,141.93 ; XC4.2 64.62,140.55 ; XC4.2 63.25,139.18 ; C6.4 395.19,90.56 ; C6.4 393.33,88.71 ; C6.4 397.04,88.71 ; C6.4 395.19,86.85 ; 395.19,66.56 C6.2 ; C6.2 395.19,70.26 ; C6.2 393.33,68.41 ; C6.2 397.04,68.41 ; 63.25,109.53 XC8.2 ; XC8.2 61.87,110.91 ; XC8.2 64.62,110.91 ; XC8.2 63.25,112.28 ; C6.6 397.04,109.01 ; C6.6 395.19,107.15 ; C6.6 395.19,110.86 ; C6.6 393.33,109.01
  TOP w1.27: XL1.3 47.7,178.68 ; XL1.3 47.7,169.08 ; XL1.3 52.5,173.88 ; XL2.4 47.7,79.84 ; XL2.4 47.7,70.24 ; XL2.4 52.5,75.04
  ART02 w0.508: XA6.5 41.44,232.88 ; XA6.5 39.84,232.88 ; XA6.5 41.44,234.48 ; XA6.5 39.84,234.48 ; XC8.2 63.25,112.02 ; XC8.2 64.36,110.91 ; XC8.2 63.25,109.79 ; XC8.2 62.13,110.91 ; 395.19,86.85 C6.4 ; C6.4 397.04,88.71 ; C6.4 395.19,90.56 ; C6.4 393.33,88.71 ; 342.68,185.32 C5.2 ; C5.2 342.68,189.03 ; C5.2 344.54,187.18 ; C5.2 340.83,187.18 ; XA5.16 331.76,123.48 ; XA5.16 332.02,122.68 ; XA5.16 330.96,123.74 ; C5.6 342.68,148.43 ; C5.6 344.54,146.58 ; C5.6 342.68,144.72 ; C5.6 340.83,146.58 ; 82.3,129.26 C2.2 ; C2.2 82.3,131.69 ; C2.2 83.52,130.47 ; C2.2 81.08,130.47 ; 342.68,165.02 C5.4 ; C5.4 344.54,166.88 ; C5.4 342.68,168.73 ; C5.4 340.83,166.88 ; 42.38,232.88 XA6.7 ; XA6.7 43.98,232.88 ; XA6.7 42.38,234.48 ; XA6.7 43.98,234.48 ; 395.19,107.15 C6.6 ; C6.6 395.19,110.86 ; C6.6 393.33,109.01 ; C6.6 397.04,109.01 ; 81.08,120.99 C4.2 ; C4.2 82.3,122.2 ; C4.2 83.52,120.99 ; C4.2 82.3,119.77 ; XA6.8 43.98,237.02 ; XA6.8 43.98,235.42 ; XA6.8 42.38,235.42 ; XA6.8 42.38,237.02 ; 63.25,139.44 XC4.2 ; XC4.2 62.13,140.55 ; XC4.2 64.36,140.55 ; XC4.2 63.25,141.67 ; C6.2 395.19,70.26 ; C6.2 393.33,68.41 ; C6.2 395.19,66.56 ; C6.2 397.04,68.41 ; 39.84,235.42 XA6.6 ; XA6.6 41.44,235.42 ; XA6.6 41.44,237.02 ; XA6.6 39.84,237.02
  ART02 w1.27: 47.7,169.08 XL1.3 ; XL1.3 47.7,178.68 ; XL1.3 42.9,173.88 ; XL1.3 52.5,173.88 ; 42.9,75.04 XL2.4 ; XL2.4 52.5,75.04 ; XL2.4 47.7,70.24 ; XL2.4 47.7,79.84
  ART03 w0.508: C5.2 344.54,187.18 ; C5.2 342.68,185.32 ; C5.2 340.83,187.18 ; C5.2 342.68,189.03 ; C5.6 344.54,146.58 ; C5.6 342.68,144.72 ; C5.6 342.68,148.43 ; C5.6 340.83,146.58 ; 342.68,165.02 C5.4 ; C5.4 342.68,168.73 ; C5.4 340.83,166.88 ; C5.4 344.54,166.88
  ART03 w1.524: XL1.3 42.62,173.88 37.15,179.36 37.15,232.16 38.67,233.68 XA6.5 ; XA6.5 XA6.7 ; XA6.5 XA6.6 XA6.8
  BOTTOM w0.508: 82.3,119.51 C4.2 ; C4.2 80.82,120.99 ; C4.2 83.77,120.99 ; C4.2 82.3,122.46 ; 80.82,130.47 C2.2 ; C2.2 82.3,129 ; C2.2 83.77,130.47 ; C2.2 82.3,131.95 ; 340.83,146.58 C5.6 ; C5.6 342.68,144.72 ; C5.6 344.54,146.58 ; C5.6 342.68,148.43 ; 338.96,16.46 340.02,16.46 ; 338.96,16.46 339.96,17.64 ; 338.96,16.46 338.96,15.28 ; 338.96,16.46 338.96,17.64 ; C5.2 342.68,189.03 ; C5.2 344.54,187.18 ; C5.2 342.68,185.32 ; C5.2 340.83,187.18 ; C6.2 395.19,70.26 ; C6.2 393.33,68.41 ; C6.2 395.19,66.56 ; C6.2 397.04,68.41 ; 329.78,122.68 XA5.16 ; XA5.16 330.08,121.8 ; XA5.16 330.96,123.86 ; 342.68,165.02 C5.4 ; C5.4 340.83,166.88 ; C5.4 342.68,168.73 ; C5.4 344.54,166.88 ; C6.6 395.19,110.86 ; C6.6 393.33,109.01 ; C6.6 395.19,107.15 ; C6.6 397.04,109.01 ; 395.19,86.85 C6.4 ; C6.4 393.33,88.71 ; C6.4 397.04,88.71 ; C6.4 395.19,90.56
  BOTTOM w1.016: XC4.2 63.2,140.61 R34.2 ; XC8.2 63.3,110.85 R40.2
  BOTTOM w1.27: XL2.4 52.5,75.04 ; XL2.4 47.7,79.84 ; XL2.4 47.7,70.24 ; XL2.4 42.9,75.04 ; XL1.3 47.7,178.68 ; XL1.3 52.5,173.88 ; XL1.3 42.9,173.88 ; XL1.3 47.7,169.08
  BOTTOM w2.032: Q1.2 218.44,209.55 ; Q8.2 236.22,40.01 ; Q4.2 236.22,163.51 ; Q3.2 218.44,163.51 ; Q2.2 236.22,210.19 ; Q5.2 218.44,86.04 ; Q6.2 236.22,86.04 ; Q7.2 218.44,40.64
  vias: v1(73.66,223.52) v1(78.74,228.6) v1(78.74,223.52) v1(83.82,228.6) v1(83.82,223.52) v1(86.36,132.08) v1(86.36,127) v1(86.36,121.92) v1(86.36,116.84) v1(86.36,111.76) v1(86.36,106.68) v1(86.36,101.6) v1(86.36,96.52) v1(86.36,91.44) v1(88.9,228.6) v1(88.9,223.52) v1(91.44,147.32) v1(91.44,142.24) v1(91.44,137.16) v1(91.44,132.08) v1(91.44,127) v1(91.44,121.92) v1(91.44,116.84) v1(91.44,111.76) v1(91.44,106.68) v1(91.44,101.6) v1(91.44,96.52) v1(91.44,91.44) v1(91.44,86.36) v1(91.44,81.28) v1(91.44,76.2) v1(93.98,243.84) v1(93.98,238.76) v1(93.98,233.68) v1(93.98,228.6) v1(93.98,223.52) v1(96.52,200.66) v1(96.52,195.58) v1(96.52,147.32) v1(96.52,142.24) v1(96.52,137.16) v1(96.52,132.08) v1(96.52,127) v1(96.52,121.92) v1(96.52,116.84) v1(96.52,111.76) v1(96.52,106.68) v1(96.52,101.6) v1(96.52,96.52) v1(96.52,91.44) v1(96.52,86.36) v1(96.52,81.28) v1(96.52,76.2) v1(99.06,243.84) v1(99.06,238.76) v1(99.06,233.68) v1(99.06,228.6) v1(99.06,223.52) v1(101.28,147.32) v1(101.6,200.66) v1(101.6,195.58) v1(101.6,190.5) v1(101.6,142.24) v1(101.6,137.16) v1(101.6,132.08) v1(101.6,127) v1(101.6,121.92) v1(101.6,116.84) v1(101.6,111.76) v1(101.6,106.68) v1(101.6,101.6) v1(101.6,96.52) v1(101.6,91.44) v1(101.6,86.36) v1(101.6,81.28) v1(101.6,76.2) v1(104.14,243.84) v1(104.14,238.76) v1(104.14,233.68) v1(104.14,228.6) v1(104.14,223.52) v1(106.68,200.66) v1(106.68,195.58) v1(106.68,190.5) v1(106.68,132.08) v1(106.68,127) v1(106.68,121.92) v1(106.68,116.84) v1(106.68,111.76) v1(106.68,106.68) v1(106.68,101.6) v1(106.68,96.52) v1(106.68,91.44) v1(109.22,243.84) v1(109.22,238.76) v1(109.22,233.68) v1(109.22,228.6) v1(109.22,223.52) v1(109.22,48.26) v1(109.22,43.18) v1(111.76,187.96) v1(111.76,182.88) v1(111.76,132.08) v1(111.76,127) v1(111.76,121.92) v1(111.76,116.84) v1(111.76,111.76) v1(111.76,106.68) v1(111.76,101.6) v1(111.76,96.52) v1(111.76,91.44) v1(114.3,243.84) v1(114.3,238.76) v1(114.3,233.68) v1(114.3,228.6) v1(114.3,223.52) v1(114.3,53.34) v1(114.3,48.26) v1(114.3,43.18) v1(116.84,187.96) v1(116.84,182.88) v1(116.84,177.8) v1(116.84,172.72) v1(116.84,167.64) v1(116.84,162.56) v1(116.84,157.48) v1(116.84,127) v1(116.84,121.92) v1(116.84,111.76) v1(116.84,106.68) v1(116.84,101.6) v1(116.84,96.52) v1(116.84,91.44) v1(116.84,86.36) v1(119.38,243.84) v1(119.38,238.76) v1(119.38,233.68) v1(119.38,228.6) v1(119.38,223.52) v1(119.38,218.44) v1(119.38,53.34) v1(119.38,48.26) v1(119.38,43.18) v1(121.92,187.96) v1(121.92,182.88) v1(121.92,172.72) v1(121.92,167.64) v1(121.92,162.56) v1(121.92,157.48) v1(121.92,152.4) v1(121.92,127) v1(121.92,121.92) v1(121.92,111.76) v1(121.92,106.68) v1(121.92,101.6) v1(121.92,96.52) v1(121.92,91.44) v1(124.46,243.84) v1(124.46,238.76) v1(124.46,233.68) v1(124.46,228.6) v1(124.46,223.52) v1(124.46,218.44) v1(124.46,66.04) v1(124.46,60.96) v1(124.46,53.34) v1(124.46,48.26) v1(124.46,43.18) v1(127,187.96) v1(127,182.88) v1(127,177.8) v1(127,172.72) v1(127,167.64) v1(127,162.56) v1(127,157.48) v1(127,152.4) v1(127,127) v1(127,121.92) v1(127,111.76) v1(127,106.68) v1(127,101.6) v1(127,96.52) v1(127,91.44) v1(127,86.36) v1(129.54,243.84) v1(129.54,238.76) v1(129.54,233.68) v1(129.54,228.6) v1(129.54,223.52) v1(129.54,218.44) v1(129.54,71.12) v1(129.54,66.04) v1(129.54,60.96) v1(129.54,53.34) v1(129.54,48.26) v1(129.54,43.18) v1(132.08,187.96) v1(132.08,182.88) v1(132.08,177.8) v1(132.08,172.72) v1(132.08,167.64) v1(132.08,162.56) v1(132.08,157.48) v1(132.08,152.4) v1(132.08,147.32) v1(132.08,142.24) v1(132.08,137.16) v1(132.08,132.08) v1(132.08,127) v1(132.08,121.92) v1(132.08,116.84) v1(132.08,111.76) v1(132.08,106.68) v1(132.08,101.6) v1(132.08,96.52) v1(132.08,91.44) v1(132.08,86.36) v1(134.62,243.84) v1(134.62,238.76) v1(134.62,233.68) v1(134.62,228.6) v1(134.62,223.52) v1(134.62,218.44) v1(134.62,71.12) v1(134.62,66.04) v1(134.62,60.96) v1(134.62,53.34) v1(134.62,48.26) v1(134.62,43.18) v1(134.62,17.78) v1(134.62,12.7) v1(134.62,7.62) v1(137.16,182.88) v1(137.16,177.8) v1(137.16,172.72) v1(137.16,167.64) v1(137.16,162.56) v1(137.16,157.48) v1(137.16,152.4) v1(137.16,147.32) v1(137.16,142.24) v1(137.16,137.16) v1(137.16,132.08) v1(137.16,127) v1(137.16,121.92) v1(137.16,116.84) v1(137.16,111.76) v1(137.16,106.68) v1(137.16,101.6) v1(137.16,96.52) v1(137.16,91.44) v1(137.16,86.36) v1(139.7,243.84) v1(139.7,238.76) v1(139.7,233.68) v1(139.7,228.6) v1(139.7,223.52) v1(139.7,218.44) v1(139.7,58.42) v1(139.7,53.34) v1(139.7,48.26) v1(139.7,22.86) v1(139.7,17.78) v1(139.7,12.7) v1(139.7,7.62) v1(142.24,172.72) v1(142.24,167.64) v1(142.24,162.56) v1(142.24,157.48) v1(142.24,152.4) v1(142.24,147.32) v1(142.24,142.24) v1(142.24,137.16) v1(142.24,132.08) v1(142.24,127) v1(142.24,121.92) v1(142.24,116.84) v1(142.24,111.76) v1(142.24,106.68) v1(142.24,101.6) v1(142.24,96.52) v1(142.24,91.44) v1(142.24,86.36) v1(144.78,243.84) v1(144.78,238.76) v1(144.78,233.68) v1(144.78,228.6) v1(144.78,223.52) v1(144.78,218.44) v1(144.78,53.34) v1(144.78,48.26) v1(144.78,22.86) v1(144.78,17.78) v1(144.78,12.7) v1(144.78,7.62) v1(147.32,172.72) v1(147.32,167.64) v1(147.32,162.56) v1(147.32,157.48) v1(147.32,152.4) v1(147.32,147.32) v1(147.32,142.24) v1(147.32,137.16) v1(147.32,132.08) v1(147.32,127) v1(147.32,121.92) v1(147.32,116.84) v1(147.32,111.76) v1(147.32,106.68) v1(147.32,101.6) v1(147.32,96.52) v1(147.32,91.44) v1(147.32,86.36) v1(149.86,243.84) v1(149.86,238.76) v1(149.86,233.68) v1(149.86,228.6) v1(149.86,223.52) v1(149.86,218.44) v1(149.86,53.34) v1(149.86,48.26) v1(149.86,27.94) v1(149.86,22.86) v1(149.86,17.78) v1(149.86,12.7) v1(149.86,7.62) v1(152.4,172.72) v1(152.4,167.64) v1(152.4,162.56) v1(152.4,157.48) v1(152.4,152.4) v1(152.4,147.32) v1(152.4,142.24) v1(152.4,137.16) v1(152.4,132.08) v1(152.4,127) v1(152.4,121.92) v1(152.4,116.84) v1(152.4,111.76) v1(152.4,106.68) v1(152.4,101.6) v1(152.4,96.52) v1(152.4,91.44) v1(152.4,86.36) v1(154.94,243.84) v1(154.94,238.76) v1(154.94,233.68) v1(154.94,228.6) v1(154.94,223.52) v1(154.94,218.44) v1(154.94,27.94) v1(154.94,22.86) v1(154.94,17.78) v1(154.94,12.7) v1(154.94,7.62) v1(157.48,172.72) v1(157.48,167.64) v1(157.48,162.56) v1(157.48,157.48) v1(157.48,152.4) v1(157.48,147.32) v1(157.48,142.24) v1(157.48,137.16) v1(157.48,132.08) v1(157.48,127) v1(157.48,121.92) v1(157.48,111.76) v1(157.48,106.68) v1(157.48,101.6) v1(157.48,96.52) v1(157.48,91.44) v1(157.48,86.36) v1(160.02,228.6) v1(160.02,223.52) v1(160.02,218.44) v1(160.02,27.94) v1(160.02,22.86) v1(160.02,17.78) v1(160.02,12.7) v1(160.02,7.62) v1(162.56,106.68) v1(162.56,101.6) v1(162.56,96.52) v1(162.56,91.44) v1(162.56,86.36) v1(162.56,81.28) v1(165.1,228.6) v1(165.1,223.52) v1(165.1,218.44) v1(167.64,106.68) v1(167.64,101.6) v1(167.64,96.52) v1(167.64,91.44) v1(167.64,86.36) v1(167.64,81.28) v1(170.18,223.52) v1(170.18,218.44) v1(172.72,137.16) v1(172.72,132.08) v1(172.72,127) v1(172.72,106.68) v1(172.72,101.6) v1(172.72,96.52) v1(172.72,91.44) v1(172.72,86.36) v1(172.72,81.28) v1(177.8,132.08) v1(177.8,127) v1(180.34,167.64) v1(180.34,162.56) v1(180.34,157.48) v1(182.88,132.08) v1(182.88,127) v1(185.42,167.64) v1(185.42,162.56) v1(185.42,157.48) v1(190.5,167.64) v1(190.5,162.56) v1(190.5,157.48) v1(213.36,208.28) v1(213.36,203.2) v1(215.46,167.39) v1(215.46,162.31) v1(218.44,203.2) v1(220.54,167.39) v1(220.54,162.31) v1(223.52,208.28) v1(223.52,203.2) v1(225.62,167.39) v1(225.62,162.31) v1(228.6,208.28) v1(228.6,203.2) v1(230.7,167.39) v1(230.82,162.56) v1(233.68,208.28) v1(233.68,203.2) v1(235.78,167.39) v1(238.76,208.28) v1(238.76,203.2) v1(240.86,167.39) v1(240.86,162.31) v1(243.84,208.28) v1(243.84,203.2) v1(245.94,167.39) v1(245.94,162.31) v1(248.48,238.51) v1(248.48,157.23) v1(248.48,152.15) v1(248.48,147.07) v1(248.92,233.68) v1(248.92,228.6) v1(248.92,223.52) v1(248.92,218.44) v1(248.92,213.36) v1(248.92,208.28) v1(248.92,203.2) v1(251.02,167.39) v1(251.02,162.31) v1(251.02,7.37) v1(253.56,157.23) v1(253.56,152.15) v1(253.56,147.07) v1(254,233.68) v1(254,228.6) v1(254,223.52) v1(254,218.44) v1(254,213.36) v1(254,208.28) v1(254,203.2) v1(256.1,167.39) v1(256.1,162.31) v1(256.1,108.97) v1(258.64,243.59) v1(261.18,103.89) v1(261.18,98.81) v1(261.18,93.73) v1(261.18,88.65) v1(261.18,42.93) v1(261.18,37.85) v1(261.18,32.77) v1(261.18,27.69) v1(261.18,22.61) v1(261.18,17.53) v1(263.63,243.31) v1(264.07,228.32) v1(264.07,223.24) v1(264.07,218.16) v1(264.07,213.08) v1(264.13,208.07) v1(329.76,60.71) v1(329.76,55.63) v1(329.76,50.55) v1(334.84,60.71) v1(334.84,55.63) v1(334.84,50.55) v1(339.73,124.14) v1(339.92,117.54) v1(339.92,55.63) v1(339.92,50.55) v1(345,122.62) v1(345,117.54) v1(379.41,17.91) v1(379.41,15.37) v1(379.41,12.83) v1(379.41,10.29) v1(379.41,7.75) v1(379.41,5.21) v1(381.95,17.91) v1(381.95,15.37) v1(381.95,12.83) v1(381.95,10.29) v1(381.95,7.75) v1(381.95,5.21) v1(384.49,17.91) v1(384.49,5.21) v1(387.03,17.91) v1(387.03,5.21) v1(389.57,17.91) v1(389.57,5.21) v1(392.11,17.91) v1(392.11,15.37) v1(392.11,12.83) v1(392.11,10.29) v1(392.11,7.75) v1(392.11,5.21) v1(394.65,17.91) v1(394.65,15.37) v1(394.65,12.83) v1(394.65,10.29) v1(394.65,7.75) v1(394.65,5.21)
PWM1H: length 156.7
  ART02 w0.508: XA5.3 276.86,118.86 277.93,117.79 281.31,117.79 284.16,120.65 284.16,125.41 282.26,127.32 261.18,127.32 260.03,126.17 v1(260.03,125.41)
  ART03 w0.508: XA1.4 261.62,233.68 260.03,232.09 v1(260.03,125.41)
PWM1L: length 42.7
  ART02 w0.508: v1(261.3,134.62) 267.33,134.62 XA2.4 ; v1(261.94,123.51) 261.94,125.22 262.45,125.73 277.62,125.73 278.13,125.22 278.13,121.92 279.4,120.65 XA5.5
  ART03 w0.508: v1(261.94,123.51) 261.94,124.45 261.3,125.08 v1(261.3,134.62)
PWM2H: length 23.3
  ART02 w0.508: v1(265.43,121.28) 266.09,121.95 266.41,121.95 267.14,122.68 XA5.2
  ART03 w0.508: XA3.4 267.33,109.22 265.43,111.12 v1(265.43,121.28)
PWM2L: length 145.1
  ART02 w0.508: v1(263.84,122.24) 265.75,124.14 274.95,124.14 276.42,122.68 XA5.4
  ART03 w0.508: XA4.4 257.18,8.89 254.95,11.11 254.95,105.73 258.13,108.9 260.96,108.9 263.84,111.79 v1(263.84,122.24)
V_IN_SENSE: length 157.5
  ART02 w0.508: v1(312.55,244.66) 322.24,244.66 350.36,216.53 350.36,132.23 338.28,120.14 XA5.19
  BOTTOM w1.016: v1(312.55,244.66) 311.6,243.71 308.56,243.71
V_OUT_SENSE: length 152.1
  TOP w1.016: v1(323.53,245.11) 323.98,244.67 R11.2
  ART02 w0.508: v1(323.53,245.11) 351.47,217.17 351.47,131.76 337.82,118.11 334.64,118.11 333.42,119.34 333.42,120.06 XA5.17
N00134: length 30.2
  TOP w0.508: XC1.1 11.53,214.41 ; XC1.1 10.16,215.78 ; XC1.1 8.79,214.41 ; XC1.1 10.16,213.04
  TOP w1.27: 25.7,187.08 XL1.1 ; XL1.1 20.9,191.88 ; XL1.1 25.7,196.68 ; XL1.1 30.5,191.88
  BOTTOM w0.508: XC1.1 11.53,214.41 ; XC1.1 10.16,213.04 ; XC1.1 10.16,215.78 ; XC1.1 8.79,214.41
  vias: v1(4.76,246.51) v1(4.76,243.97) v1(4.76,241.43) v1(4.76,238.89) v1(4.76,236.35) v1(4.76,233.81) v1(7.3,246.51) v1(7.3,243.97) v1(7.3,241.43) v1(7.3,238.89) v1(7.3,236.35) v1(7.3,233.81) v1(9.84,246.51) v1(9.84,233.81) v1(12.38,246.51) v1(12.38,233.81) v1(14.92,246.51) v1(14.92,233.81) v1(17.46,246.51) v1(17.46,243.97) v1(17.46,241.43) v1(17.46,238.89) v1(17.46,236.35) v1(17.46,233.81) v1(20,246.51) v1(20,243.97) v1(20,241.43) v1(20,238.89) v1(20,236.35) v1(20,233.81)
N00143: length 39.1
  TOP w0.508: XC2.2 11.53,151.35 ; XC2.2 10.16,152.72 ; XC2.2 8.79,151.35 ; XC2.2 10.16,149.98
  TOP w1.27: XL1.2 30.5,173.88 ; XL1.2 25.7,178.68 ; XL1.2 25.7,169.08 ; XL1.2 20.9,173.88
  ART02 w0.508: XC2.2 11.28,151.35 ; XC2.2 9.04,151.35 ; XC2.2 10.16,152.47 ; XC2.2 10.16,150.23
  ART03 w0.508: 9.04,151.35 XC2.2 ; XC2.2 10.16,152.47 ; XC2.2 10.16,150.23 ; XC2.2 11.28,151.35
  BOTTOM w0.508: XC2.2 10.16,152.72 ; XC2.2 11.53,151.35 ; XC2.2 10.16,149.98 ; XC2.2 8.79,151.35
  vias: v1(5.08,143.64) v1(5.08,141.1) v1(5.08,138.56) v1(5.08,136.02) v1(5.08,133.48) v1(5.08,130.94) v1(7.62,143.64) v1(7.62,141.1) v1(7.62,138.56) v1(7.62,136.02) v1(7.62,133.48) v1(7.62,130.94) v1(10.16,143.64) v1(10.16,130.94) v1(12.7,143.64) v1(12.7,130.94) v1(15.24,143.64) v1(15.24,130.94) v1(17.78,143.64) v1(17.78,141.1) v1(17.78,138.56) v1(17.78,136.02) v1(17.78,133.48) v1(17.78,130.94) v1(20.32,143.64) v1(20.32,141.1) v1(20.32,138.56) v1(20.32,136.02) v1(20.32,133.48) v1(20.32,130.94)
N00161: length 28.9
  ART02 w0.508: 9.04,178.85 XC2.1 ; XC2.1 10.16,179.97 ; XC2.1 10.16,177.73 ; XC2.1 11.28,178.85 ; XC1.2 10.16,188.03 ; XC1.2 10.16,185.79 ; XC1.2 11.28,186.91 ; XC1.2 9.04,186.91
  ART03 w0.508: 9.04,186.91 XC1.2 ; XC1.2 10.16,185.79 ; XC1.2 11.28,186.91 ; XC1.2 10.16,188.03 ; XC2.1 10.16,179.97 ; XC2.1 11.28,178.85 ; XC2.1 9.04,178.85 ; XC2.1 10.16,177.73
  BOTTOM w0.508: XC1.2 10.16,188.28 ; XC1.2 10.16,185.54 ; XC1.2 11.53,186.91 ; XC1.2 8.79,186.91 ; XC2.1 10.16,180.22 ; XC2.1 8.79,178.85 ; XC2.1 10.16,177.48 ; XC2.1 11.53,178.85
N00267: length 38.9
  ART02 w0.508: 81.08,167.98 C2.1 ; C2.1 82.3,169.19 ; C2.1 83.52,167.98 ; C2.1 82.3,166.76 ; XC4.1 64.36,168.06 ; XC4.1 63.25,169.17 ; XC4.1 62.13,168.06 ; XC4.1 63.25,166.94 ; 81.08,173.53 C1.2 ; C1.2 82.3,172.31 ; C1.2 82.3,174.75 ; C1.2 83.52,173.53 ; XC3.2 64.36,173.45 ; XC3.2 63.25,174.57 ; XC3.2 63.25,172.33 ; XC3.2 62.13,173.45
  BOTTOM w1.016: R32.1 63.2,161.59 63.25,161.65 XC4.1 ; R31.2 63.2,178.13 63.25,178.08 XC3.2
N01331: length 6.1
  BOTTOM w1.016: FB1.2 Q1.4 213.36,215.46 C19.1
N01554: length 8.1
  BOTTOM w1.016: R1.1 R7.2 214.95,220.66 215.9,219.71 Q1.3 215.9,215.46 C19.2
N02735: length 9.1
  BOTTOM w1.016: D12.1 189.99,238.33 D11.3 189.99,243.08 188.85,244.22 CT1.3
N02836: length 94.7
  TOP w2.54: 241.3,232.41 Q2.1 ; Q1.1 223.52,223.2 227.01,226.69 228.28,226.69 232.09,230.5 232.09,232.41
  TOP w3.81: 241.3,232.41 236.7,237.01 232.09,232.41
  TOP w7.62: 236.7,237.01 236.7,237.33 228.92,245.11 214.88,245.11 CT1.2
N003141: length 2.3
  BOTTOM w1.016: R29.2 R30.1
N03399: length 164.6
  TOP w7.62: L1.1 172.01,234.03 173.28,234.03 173.32,233.98 173.69,233.98 178.69,228.98 CT1.1 188.59,201.61 193.36,196.85 197.17,196.85 199.39,194.63 209.55,194.63 209.87,194.31 257.49,194.31 260.03,196.85 285.43,196.85 287.02,198.44 287.02,205.74
N03711: length 6.4
  BOTTOM w1.016: FB2.2 Q2.4 231.14,215.16 C9.1
N03751: length 8.4
  BOTTOM w1.016: R2.1 R10.2 232.73,220.66 233.68,219.71 Q2.3 233.68,215.16 C9.2
N004301: length 2.3
  BOTTOM w1.016: R30.2 R31.1
N004861: length 2.3
  BOTTOM w1.016: R33.1 R32.2
N005141: length 2.3
  BOTTOM w1.016: R33.2 R34.1
N05226: length 5.2
  TOP w1.016: R12.2 339.38,247.46 339.23,247.31 338.07,247.31 338.05,247.33 337.08,247.33 336.96,247.46 R63.1
N05349: length 117.7
  TOP w0.508: D32.1 312.9,31.11 ; D32.1 311.4,28.73 ; D32.1 311.4,33.5 ; D32.1 309.9,31.11 ; 311.4,153.19 D30.1 ; D30.1 312.9,155.57 ; D30.1 311.4,157.96 ; D30.1 309.9,155.57 ; 340.83,109.01 C6.5 ; C6.5 342.68,107.15 ; C6.5 344.54,109.01 ; C5.3 397.04,166.88 ; C5.3 395.19,168.73 ; C5.3 395.19,165.02 ; C5.3 393.33,166.88 ; C6.3 342.68,90.56 ; C6.3 340.83,88.71 ; C6.3 344.54,88.71 ; C6.3 342.68,86.85 ; 320.83,217.81 D29.1 ; D29.1 322.33,220.19 ; D29.1 322.33,215.42 ; D29.1 323.83,217.81 ; C5.1 397.04,187.18 ; C5.1 393.33,187.18 ; C5.1 395.19,189.03 ; C5.1 395.19,185.32 ; D31.1 322.33,95.73 ; D31.1 323.83,93.34 ; D31.1 320.83,93.34 ; D31.1 322.33,90.96 ; 393.33,146.58 C5.5 ; C5.5 395.19,148.43 ; C5.5 397.04,146.58 ; C5.5 395.19,144.72 ; C6.1 344.54,68.41 ; C6.1 342.68,70.26 ; C6.1 340.83,68.41
  TOP w1.016: 367.03,246.38 365.95,247.46 R59.1
  BOTTOM w0.508: C5.1 395.19,189.03 ; C5.1 397.04,187.18 ; C5.1 393.33,187.18 ; C5.1 395.19,185.32 ; 393.33,146.58 C5.5 ; C5.5 395.19,144.72 ; C5.5 395.19,148.43 ; C5.5 397.04,146.58 ; C5.3 397.04,166.88 ; C5.3 393.33,166.88 ; C5.3 395.19,165.02 ; C5.3 395.19,168.73
  BOTTOM w1.016: R41.1 311.51,26.99 311.4,27.09 D32.1
  vias: v1(379.41,246.51) v1(379.41,243.97) v1(379.41,241.43) v1(379.41,238.89) v1(379.41,236.35) v1(379.41,233.81) v1(381.95,246.51) v1(381.95,243.97) v1(381.95,241.43) v1(381.95,238.89) v1(381.95,236.35) v1(381.95,233.81) v1(384.49,246.51) v1(384.49,233.81) v1(387.03,246.51) v1(387.03,233.81) v1(389.57,246.51) v1(389.57,233.81) v1(392.11,246.51) v1(392.11,243.97) v1(392.11,241.43) v1(392.11,238.89) v1(392.11,236.35) v1(392.11,233.81) v1(394.65,246.51) v1(394.65,243.97) v1(394.65,241.43) v1(394.65,238.89) v1(394.65,236.35) v1(394.65,233.81)
N08439: length 6.1
  BOTTOM w1.016: C20.1 223.01,158.06 223.52,157.56 Q3.4 FB3.2
N08479: length 8.2
  BOTTOM w1.016: R13.2 221.93,153.03 220.98,153.99 ; 220.98,153.99 220.34,153.35 R3.1 ; 220.98,153.99 Q3.3 220.98,157.56 221.49,158.06 C20.2
N08627: length 9.2
  BOTTOM w1.016: D16.1 189.99,134.41 D15.3 189.99,129.67 CT2.4
N08631: length 58.8
  TOP w2.54: 230.82,152.08 231.14,152.4 Q4.1 ; 213.36,148.27 Q3.1
  TOP w3.81: 212.25,139.54 216.22,143.51 ; 216.22,143.51 213.36,146.37 213.36,148.27 ; 216.22,143.51 216.85,143.51 217.49,142.88 221.62,142.88 221.93,143.19 226.06,143.19 229.87,147 229.87,150.5 230.82,151.45 230.82,152.08
  TOP w7.62: 212.25,139.54 202.56,139.54 198.75,143.35 CT2.1
N08663: length 173.8
  TOP w7.62: CT2.2 180.75,143.51 168.2,156.06 168.2,169.56 167.06,170.7 167.06,178.02 L2.1 276.11,178.78 286.12,168.76 286.12,168.59 286.7,168.59
N08687: length 6.2
  BOTTOM w1.016: C10.1 240.79,157.99 241.3,157.48 Q4.4 240.98,155.26 FB4.2
N08743: length 7.9
  BOTTOM w1.016: 239.18,152.53 R4.1 ; 239.18,152.53 239.18,155.15 Q4.3 238.82,155.64 238.82,157.8 239.27,158.24 C10.2 ; 239.18,152.53 R16.2
N09826: length 5.3
  BOTTOM w1.016: R43.2 R44.1
N10005: length 5.3
  TOP w1.016: R64.1 333.04,244.69 333.07,244.67 R63.2
N10007: length 5.2
  TOP w1.016: R60.2 349.54,247.46 349.39,247.31 347.27,247.31 347.12,247.46 R61.1
N12168: length 30.2
  TOP w0.508: XC5.1 10.16,35.88 ; XC5.1 10.16,33.14 ; XC5.1 11.53,34.51 ; XC5.1 8.79,34.51
  TOP w1.27: XL2.2 25.7,61.84 ; XL2.2 25.7,52.24 ; XL2.2 30.5,57.04 ; XL2.2 20.9,57.04
  BOTTOM w0.508: XC5.1 10.16,35.88 ; XC5.1 10.16,33.14 ; XC5.1 8.79,34.51 ; XC5.1 11.53,34.51
  vias: v1(4.76,17.59) v1(4.76,15.05) v1(4.76,12.51) v1(4.76,9.97) v1(4.76,7.43) v1(4.76,4.89) v1(7.3,17.59) v1(7.3,15.05) v1(7.3,12.51) v1(7.3,9.97) v1(7.3,7.43) v1(7.3,4.89) v1(9.84,17.59) v1(9.84,4.89) v1(12.38,17.59) v1(12.38,4.89) v1(14.92,17.59) v1(14.92,4.89) v1(17.46,17.59) v1(17.46,15.05) v1(17.46,12.51) v1(17.46,9.97) v1(17.46,7.43) v1(17.46,4.89) v1(20,17.59) v1(20,15.05) v1(20,12.51) v1(20,9.97) v1(20,7.43) v1(20,4.89)
N12176: length 39.1
  TOP w0.508: XC6.2 11.53,97.57 ; XC6.2 10.16,98.94 ; XC6.2 8.79,97.57 ; XC6.2 10.16,96.2
  TOP w1.27: XL2.1 25.7,79.84 ; XL2.1 30.5,75.04 ; XL2.1 20.9,75.04 ; XL2.1 25.7,70.24
  ART02 w0.508: 9.04,97.57 XC6.2 ; XC6.2 10.16,98.69 ; XC6.2 10.16,96.45 ; XC6.2 11.28,97.57
  ART03 w0.508: XC6.2 10.16,98.69 ; XC6.2 9.04,97.57 ; XC6.2 10.16,96.45 ; XC6.2 11.28,97.57
  BOTTOM w0.508: 8.79,97.57 XC6.2 ; XC6.2 11.53,97.57 ; XC6.2 10.16,98.94 ; XC6.2 10.16,96.2
  vias: v1(5.08,118.24) v1(5.08,115.7) v1(5.08,113.16) v1(5.08,110.62) v1(5.08,108.08) v1(5.08,105.54) v1(7.62,118.24) v1(7.62,115.7) v1(7.62,113.16) v1(7.62,110.62) v1(7.62,108.08) v1(7.62,105.54) v1(10.16,118.24) v1(10.16,105.54) v1(12.7,118.24) v1(12.7,105.54) v1(15.24,118.24) v1(15.24,105.54) v1(17.78,118.24) v1(17.78,115.7) v1(17.78,113.16) v1(17.78,110.62) v1(17.78,108.08) v1(17.78,105.54) v1(20.32,118.24) v1(20.32,115.7) v1(20.32,113.16) v1(20.32,110.62) v1(20.32,108.08) v1(20.32,105.54)
N12212: length 28.9
  ART02 w0.508: 9.04,62.01 XC5.2 ; XC5.2 10.16,60.89 ; XC5.2 11.28,62.01 ; XC5.2 10.16,63.13 ; 10.16,68.95 XC6.1 ; XC6.1 11.28,70.07 ; XC6.1 10.16,71.19 ; XC6.1 9.04,70.07
  ART03 w0.508: 10.16,60.89 XC5.2 ; XC5.2 11.28,62.01 ; XC5.2 9.04,62.01 ; XC5.2 10.16,63.13 ; XC6.1 10.16,71.19 ; XC6.1 10.16,68.95 ; XC6.1 9.04,70.07 ; XC6.1 11.28,70.07
  BOTTOM w0.508: XC5.2 10.16,63.38 ; XC5.2 8.79,62.01 ; XC5.2 10.16,60.64 ; XC5.2 11.53,62.01 ; 8.79,70.07 XC6.1 ; XC6.1 10.16,68.7 ; XC6.1 11.53,70.07 ; XC6.1 10.16,71.44
N12260: length 38.9
  ART02 w0.508: C3.2 82.3,79.15 ; C3.2 81.08,77.93 ; C3.2 82.3,76.71 ; C3.2 83.52,77.93 ; XC8.1 63.25,84.52 ; XC8.1 64.36,83.4 ; XC8.1 63.25,82.29 ; XC8.1 62.13,83.4 ; XC7.2 63.18,79.1 ; XC7.2 63.18,76.86 ; XC7.2 62.06,77.98 ; XC7.2 64.3,77.98 ; 82.3,82.27 C4.1 ; C4.1 83.52,83.48 ; C4.1 82.3,84.7 ; C4.1 81.08,83.48
  BOTTOM w1.016: 63.3,67.94 63.3,77.67 63.18,77.78 XC7.2 ; XC8.1 63.25,89.12 63.3,89.17 R38.1
N12524: length 6.1
  BOTTOM w1.016: C21.1 213.36,91 Q5.4 FB5.2
N12564: length 8.2
  BOTTOM w1.016: R19.2 214.95,95.89 215.9,94.93 ; 215.9,94.93 Q5.3 215.9,91 C21.2 ; 215.9,94.93 216.53,95.57 R5.1
N12712: length 9.2
  BOTTOM w1.016: CT3.3 189.99,119.25 D19.3 189.99,114.51 D20.1
N12716: length 93.8
  TOP w2.54: 241.3,103.03 Q6.1 ; 226.7,102.23 223.52,99.06 Q5.1
  TOP w3.81: 235.03,109.3 235.03,112.95 234.95,113.03 ; 235.03,109.3 241.3,103.03 ; 235.03,109.3 234.55,109.3 232.09,106.84 232.09,106.05 228.28,102.23 226.7,102.23
  TOP w7.62: CT3.2 201.61,108.27 203.2,108.27 218.44,123.51 227.01,123.51 234.95,115.57 234.95,113.03
N12748: length 170.3
  TOP w7.62: 287.02,81.28 286.7,80.96 286.7,77.79 279.08,70.17 191.14,70.17 183.51,77.79 183.51,100.33 CT3.1 176.19,117.82 L3.1
N12776: length 6.5
  BOTTOM w1.016: FB6.2 231.14,96.27 Q6.4 231.14,91.12 C22.1
N12832: length 8.3
  BOTTOM w1.016: 234,96.52 233.93,96.58 R22.2 ; 234,96.52 234,93.66 Q6.3 233.68,90.87 C22.2 ; 234,96.52 R6.1
N13072: length 5.8
  BOTTOM w1.016: FB7.2 223.49,31.09 Q7.4 223.52,33.12 223.01,33.63 C23.1
N13096: length 7.9
  BOTTOM w1.016: R8.1 220.37,28.92 220.98,29.53 220.98,29.84 ; R25.2 221.91,28.92 220.98,29.84 ; 220.98,29.84 Q7.3 220.98,33.12 221.49,33.63 C23.2
